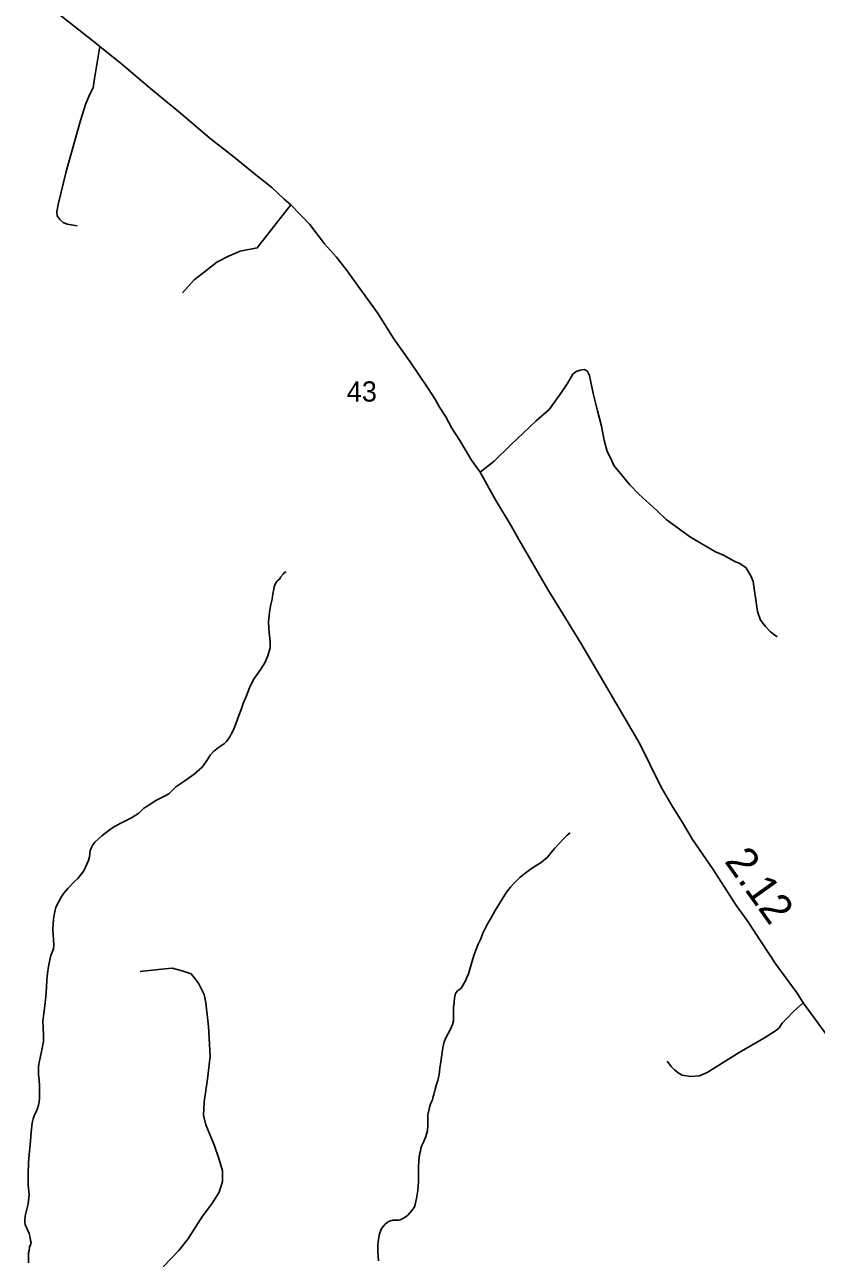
# Model space of a CAD drawing. Extents: x 2220236 to 2384410, y 720751 to 894131.
# Drawn here: x 2311292 to 2314497, y 870069 to 875066 of the extents above; entities that cross this region are included whole.
import ezdxf

# ---------------------------------------------------------------- set-up
doc = ezdxf.new("R2010")
doc.units = 0
doc.layers.add('Default', color=7, linetype='Continuous')

msp = doc.modelspace()

# ---------------------------------------------------------------- linework, layer by layer
at = {"layer": 'Default'}
for points in [[(2314558, 870947.4), (2314444.3, 871104.2), (2314419.9, 871143.8), (2314332.6, 871260.9), (2314216.9, 871437.6), (2314174.3, 871497.1), (2314076.7, 871647.9), (2313995.4, 871765), (2313954.7, 871834.6), (2313916, 871896), (2313869.2, 871977.6), (2313783, 872152.5), (2313620.5, 872430.4), (2313544.3, 872560.8), (2313481.6, 872662.5), (2313410.5, 872777.7), (2313292.7, 872981), (2313262, 873036.7), (2313198.8, 873142), (2313135.6, 873253.2), (2313101.2, 873302.8), (2313054.3, 873382.4), (2313021.8, 873432), (2312997.4, 873477.7), (2312970.9, 873517.4), (2312954.7, 873547.1), (2312926.2, 873592.8), (2312853, 873700), (2312785.9, 873793.3), (2312720.5, 873899.3), (2312649.4, 873997.6), (2312596.9, 874068.8), (2312554.6, 874124.7), (2312505.5, 874178.9), (2312446.2, 874256.8), (2312369.7, 874336.2), (2312342.6, 874359.9), (2312292.9, 874406.2), (2312220.7, 874463.8), (2312140.5, 874529.4), (2312041.2, 874607.3), (2311922.7, 874707.8), (2311809.8, 874801.6), (2311685, 874906.6), (2311595.9, 874978.6), (2311567.6, 875001.5), (2311409.6, 875124.6)], [(2311504.8, 874251.8), (2311464.1, 874258.5), (2311447.2, 874265.3), (2311433.7, 874277.2), (2311423.5, 874292.4), (2311421.8, 874307.7), (2311426.9, 874338.2), (2311459.1, 874472), (2311518.3, 874678.7), (2311538.6, 874743.1), (2311553.9, 874782.1), (2311569.1, 874810.9), (2311574.2, 874848.2), (2311595.9, 874978.6)], [(2311930.6, 873980.7), (2311978, 874033.2), (2312018.7, 874063.7), (2312069.5, 874104.4), (2312116.9, 874128.1), (2312164.3, 874148.4), (2312233.7, 874162), (2312309.8, 874261.6), (2312369.7, 874336.2)], [(2313135.6, 873253.2), (2313193.2, 873297.8), (2313260.5, 873364.6), (2313363.4, 873461.7), (2313414.9, 873508.2), (2313464.2, 873574.6), (2313491.7, 873615), (2313511.2, 873651.2), (2313525.2, 873661.4), (2313541, 873667.4), (2313557.1, 873669.7), (2313569.2, 873663.8), (2313579.3, 873645.8), (2313594.1, 873572), (2313610.8, 873502.2), (2313627.5, 873440.5), (2313638.1, 873382.7), (2313650.6, 873336.8), (2313664.9, 873309), (2313677.1, 873281), (2313742, 873201.9), (2313778.3, 873164.1), (2313853.1, 873097), (2313889.4, 873061.4), (2313988.1, 872990.5), (2314088.8, 872931.6), (2314121, 872917.9), (2314169.3, 872890.5), (2314185.4, 872884.7), (2314211.5, 872867), (2314233.8, 872831.3), (2314242, 872811.2), (2314259.4, 872689.5), (2314271.7, 872653.7), (2314291.9, 872628), (2314312.2, 872606.2), (2314338.5, 872586.5)], [(2312350.3, 872850.2), (2312344.3, 872846.6), (2312338.3, 872840.7), (2312328.2, 872828.7), (2312326.2, 872824.6), (2312324.3, 872822), (2312318.3, 872816.1), (2312314.3, 872812.5), (2312308.6, 872804.9), (2312304.3, 872796.5), (2312302.4, 872789.8), (2312300.4, 872780), (2312296.4, 872760.2), (2312294.3, 872738.7), (2312289, 872717.3), (2312284.2, 872696.5), (2312282.3, 872674.2), (2312279.5, 872646.2), (2312280.4, 872624.1), (2312282.4, 872604.5), (2312284.4, 872580), (2312286.3, 872561.9), (2312286.3, 872542.3), (2312276.7, 872509.9), (2312264.2, 872481.5), (2312248.3, 872456.3), (2312218.2, 872414), (2312202.3, 872380.6), (2312188.2, 872344.6), (2312176.2, 872316.3), (2312168.2, 872292.1), (2312158.9, 872267.9), (2312146.3, 872234.6), (2312139.5, 872216.3), (2312134.3, 872204.5), (2312127.6, 872192), (2312122.3, 872182), (2312116.1, 872171.7), (2312108.6, 872162.4), (2312100.2, 872153.9), (2312076.2, 872138.1), (2312056.5, 872122.7), (2312044.2, 872108.2), (2312024.3, 872077.8), (2312010.1, 872058.4), (2311978.2, 872030), (2311940.3, 872003.7), (2311904.1, 871978.6), (2311876.1, 871950.2), (2311858, 871940.5), (2311826.1, 871924.4), (2311804.2, 871912.1), (2311790.2, 871902.5), (2311774.2, 871892), (2311754.2, 871872.2), (2311724.1, 871853.8), (2311686.1, 871834.2), (2311656, 871818.1), (2311634.2, 871804), (2311604.1, 871780), (2311576, 871754.2), (2311566.3, 871741.4), (2311560.5, 871730.6), (2311557.3, 871720.7), (2311554, 871695.9), (2311550, 871680.1), (2311544, 871665.9), (2311531.9, 871638.4), (2311507, 871607), (2311494, 871595.8), (2311467.9, 871568.3), (2311450, 871548), (2311440, 871532), (2311428.1, 871511.7), (2311418.1, 871491.7), (2311412.1, 871467.6), (2311408.1, 871442.8), (2311406.1, 871404.1), (2311406.5, 871379.5), (2311408.1, 871360), (2311410, 871337.9), (2311408.8, 871323), (2311406.1, 871315.5), (2311397.9, 871295.6), (2311391.9, 871271.5), (2311388.1, 871250.9), (2311384.5, 871223.6), (2311382, 871195.7), (2311379.9, 871167.6), (2311378, 871128.3), (2311374, 871093.5), (2311370, 871059.7), (2311365.9, 871031.7), (2311366.1, 871003.7), (2311367.9, 870973.6), (2311367.9, 870948), (2311357.9, 870900.2)], [(2313500.6, 871792.2), (2313487.9, 871783.4), (2313478.7, 871773.9), (2313470.6, 871766.3), (2313455.3, 871749.1), (2313438.5, 871730.4), (2313424.6, 871714.2), (2313407.2, 871693.1), (2313392.7, 871680.1), (2313382.5, 871672.3), (2313352.6, 871653.8), (2313323.6, 871633), (2313296.5, 871612.1), (2313270.6, 871585.6), (2313258.5, 871572.1), (2313242.5, 871551.7), (2313224.5, 871523.9), (2313196.6, 871477.6), (2313182.6, 871451.6), (2313162.6, 871418), (2313146.5, 871386.1), (2313138.4, 871363.7), (2313128.5, 871341.9), (2313118.5, 871317.7), (2313110.6, 871296), (2313094.5, 871239.7), (2313088.6, 871221.2), (2313082.6, 871206.4), (2313077, 871193.7), (2313072.5, 871186.2), (2313062.4, 871167.7), (2313056.5, 871160.1), (2313044.4, 871152.2), (2313038.5, 871146.2), (2313036.5, 871142.1), (2313034.5, 871136.2), (2313032.4, 871123.9), (2313030.4, 871105.6), (2313028.4, 871085.9), (2313028.5, 871077.7), (2313028.4, 871065.3), (2313028.3, 871052.3), (2313028.4, 871031.7), (2313024.4, 871015.9), (2313016.4, 870997.6), (2313006.5, 870980), (2312996.4, 870961.6), (2312990.5, 870945.7), (2312984.5, 870921.7), (2312980.4, 870893.7), (2312976.4, 870865.5), (2312972.4, 870839.9), (2312970.5, 870813.6), (2312964.5, 870789.6), (2312958.5, 870769.5), (2312954.3, 870753.7), (2312948.5, 870731.5), (2312946.4, 870724), (2312942.5, 870711.4), (2312936.4, 870698.2), (2312932.3, 870685.6), (2312928.5, 870667.5), (2312924.4, 870650.1), (2312924.4, 870640.3), (2312924.4, 870619.7), (2312924.3, 870608.3), (2312922.4, 870586), (2312920.4, 870577.7), (2312916.4, 870561.9), (2312906.3, 870540.1), (2312900.5, 870526), (2312896.5, 870515.9), (2312894.4, 870503.6), (2312890.4, 870489.4), (2312888.3, 870465.5), (2312886.3, 870436), (2312886.3, 870404), (2312886.5, 870379.4), (2312884.3, 870343.9), (2312878.4, 870311.7), (2312872.4, 870287.6), (2312870.4, 870277.7), (2312860.4, 870263.5), (2312844.3, 870245.4), (2312834.5, 870237.6), (2312822.4, 870229.9), (2312812.4, 870225.3), (2312806.4, 870223.5), (2312782.4, 870224.1), (2312764.5, 870217.5), (2312751.7, 870207.2), (2312744.4, 870199.5), (2312736.4, 870189.4), (2312734.2, 870183.5), (2312728.3, 870167.6), (2312724.4, 870145.5), (2312722.3, 870124)], [(2311759.9, 871230.9), (2311846.3, 871240.8), (2311889.5, 871244.2), (2311929.4, 871234.2), (2311965.9, 871220.9), (2311995.8, 871184.3), (2312019.1, 871137.8), (2312025.7, 871104.5), (2312035.7, 871008.1), (2312042.3, 870888.5), (2312032.4, 870795.4), (2312019.1, 870702.3), (2312015.8, 870649.1), (2312025.7, 870609.2), (2312058.9, 870529.4), (2312078.9, 870469.6), (2312092.2, 870423.1), (2312092.2, 870379.8), (2312078.9, 870336.6), (2312049, 870290.1), (2312012.4, 870240.2), (2311952.6, 870147.1), (2311916.1, 870100.6), (2311853, 870034.1)], [(2314444.3, 871104.2), (2314406.7, 871069.6), (2314375, 871037.3), (2314359.3, 871021.2), (2314347.4, 871003.2), (2314335.6, 870992.9), (2314287.9, 870962.5), (2314184.6, 870903.4), (2314055.5, 870821.9), (2314023.7, 870807.6), (2313987.8, 870805.3), (2313953.7, 870810.9), (2313937.5, 870820.7), (2313923.4, 870832.5), (2313909.3, 870846.3), (2313893.2, 870868.3)], [(2311357.9, 870900.2), (2311352, 870869.5), (2311348, 870847.9), (2311347.9, 870831.5), (2311347.9, 870811.9), (2311350, 870791.4), (2311352, 870766.1), (2311351.9, 870749.6), (2311352.3, 870728.3), (2311351.9, 870716), (2311350, 870701.9), (2311348.1, 870689.7), (2311343.9, 870675.5), (2311337.9, 870662), (2311332, 870649.6), (2311326, 870633.7), (2311321.9, 870618), (2311317.8, 870580), (2311315.8, 870545.5), (2311310, 870487.8), (2311307.8, 870457.3), (2311306, 870409.6), (2311305.8, 870365.4), (2311310, 870327.8), (2311305.9, 870290), (2311302, 870273.4), (2311295.9, 870251.8), (2311294, 870239.3), (2311291.8, 870223.8), (2311291.8, 870213.8), (2311294, 870205.7), (2311303.8, 870184), (2311309.8, 870169.5), (2311313.9, 870154), (2311316, 870141.7), (2311317.9, 870133.6), (2311315.9, 870123.7), (2311311.9, 870113.8), (2311309.8, 870101.3), (2311307.8, 870091.4), (2311307.8, 870081.6), (2311307.8, 870071.8), (2311307.9, 870051.2)], [(2312722.3, 870124), (2312722.2, 870095.4), (2312724.3, 870059.2)]]:
    msp.add_lwpolyline(points, dxfattribs=at)

# ---------------------------------------------------------------- texts
msp.add_text('43', height=82.02, dxfattribs=at).set_placement((2312595.9, 873539.6))
msp.add_text('2.12', height=125, rotation=305.6013, dxfattribs=at).set_placement((2314122.2, 871677.2))

doc.saveas('drawing.dxf')
